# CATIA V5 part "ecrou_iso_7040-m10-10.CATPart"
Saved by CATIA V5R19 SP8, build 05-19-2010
Part number: ecrou_iso_7040-m10-10
Nomenclature: 32
Source: Unknown
Description: PART-ecrou_iso_7040-m10-10-DESC
Bounding box of the stored display mesh (mm): x -9.238 to 9.238, y -8 to 8, z 0 to 11.9
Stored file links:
  C:\Users\rphgr\Desktop\0_Tapis_TC520B_vitesse\ecrou_iso_7040-m10-10.CATPart
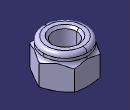
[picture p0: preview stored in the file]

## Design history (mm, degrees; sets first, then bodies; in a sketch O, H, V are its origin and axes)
AxisSystem1: origin (0, 0, 0), X (1, 0, 0), Y (0, 1, 0), Z (0, 0, 1)
Body1 "ecrou_iso_7040-m10-10" (main body)
  Solid1: solid without history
